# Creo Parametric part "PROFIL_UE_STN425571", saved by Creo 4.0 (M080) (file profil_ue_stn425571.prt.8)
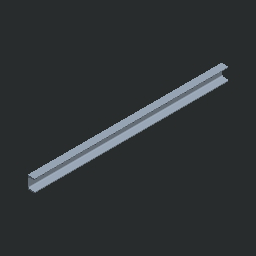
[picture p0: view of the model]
Units: millimeter Kilogram Sec (mmKs); MM, KILOGRAM, SECS
Materials in the file: OCEL_N

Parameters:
  MFG_WP_MATERIAL = "OCEL"
  NAZOV = "PROFIL_UE_STN425571"
  NORMA = "STN 42 5571"
  PTC_MATERIAL_NAME = "OCEL_N"

Other parameters: HMOTNOST, HUSTOTA, D9

Created from: UE.PRT

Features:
  1. datum plane "DTM1"
  2. datum plane "DTM2"
  3. datum plane "DTM3"

Named dimensions: male_r

Layers: 1, 2, 3, 4, 5, 6, 7, 8, 9, 10, 11, 12, 13, 14, 15, 16, 17, 18, 19, 20, 21, 22, 23, 24, 25, 26, 27, 28, 29, 30, 31, 32

Family table entries: GENERIC, PROFIL_UE_65, PROFIL_UE_STN425571, value(d_val), 2/B, value(i_val), PROFIL_UE_80, PROFIL_UE_STN425571, !/T, 2/D, PROFIL_UE_100, PROFIL_UE_STN425571, !/Y, 2/G, PROFIL_UE_120, PROFIL_UE_STN425571, !/^, 2/J, PROFIL_UE_140, PROFIL_UE_STN425571, 2/M, 2/ , PROFIL_UE_160, PROFIL_UE_STN425571, !/d, 2/P, 2/!, 2/!, 2/2, # Pro/TABLE, [] S 92;, [] W 10;, [A] W  3;, [B] W 14;, [C] W 10;, [D] W 10;, [E] W 10;, [F] W 10;, [G] W 10;, [H] W 10;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

Surfaces: 10 plane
